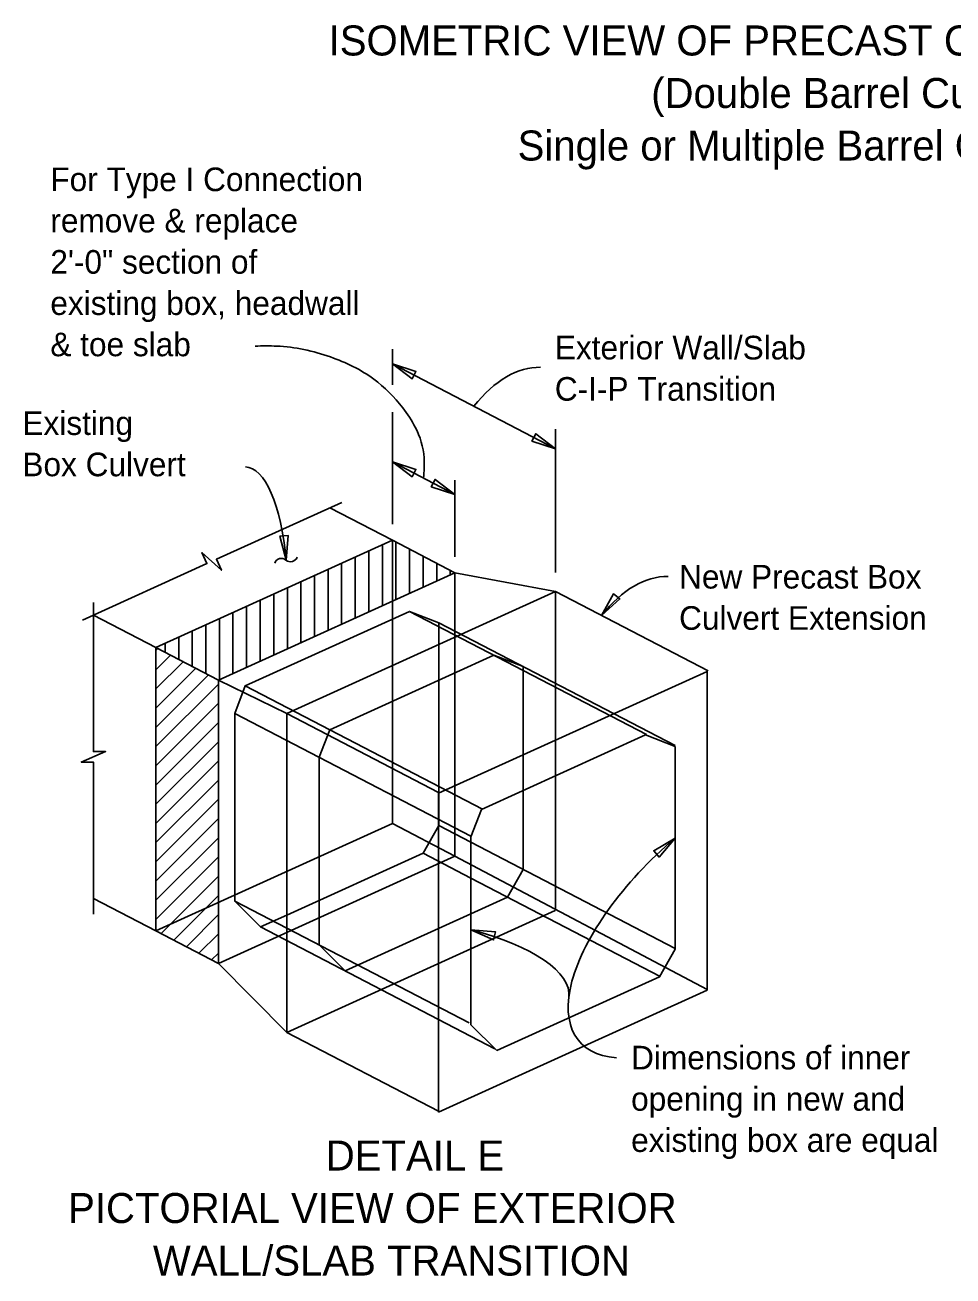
# Model space of a CAD drawing. Extents: x 10050 to 10414, y 76434 to 76519.
# Drawn here: x 10207.9 to 10231.66, y 76436.77 to 76468.78 of the extents above; entities that cross this region are included whole.
import ezdxf

# ---------------------------------------------------------------- set-up
doc = ezdxf.new("R2010")
doc.units = 0
for name, color, linetype in [('AdhocPoint_dp', 7, 'Continuous'), ('Patterning', 7, 'Continuous'), ('PlotBorder_dp', 7, 'Continuous'), ('SubStrConc_h', 7, 'Continuous'), ('Symbols', 7, 'Continuous'), ('TextMisc', 7, 'Continuous')]:
    doc.layers.add(name, color=color, linetype=linetype)

msp = doc.modelspace()

# ---------------------------------------------------------------- linework, layer by layer
at = {"layer": 'AdhocPoint_dp'}
for p, q in [((10217.307, 76455.593), (10215.707, 76456.424)), ((10211.255, 76452.848), (10209.655, 76453.679)), ((10211.255, 76445.597), (10209.655, 76446.428))]:
    msp.add_line(p, q, dxfattribs=at)
at = {"layer": 'Patterning'}
for p, q in [((10217.307, 76460.485), (10217.307, 76459.573)), ((10221.482, 76457.937), (10217.307, 76460.106)), ((10217.307, 76458.875), (10217.307, 76456.008)), ((10221.482, 76458.434), (10221.482, 76454.769)), ((10218.907, 76456.768), (10217.307, 76457.599)), ((10218.907, 76457.129), (10218.907, 76455.171))]:
    msp.add_line(p, q, dxfattribs=at)
for points in [[(10214.584, 76455.086), (10214.638, 76455.717), (10214.427, 76455.7)], [(10222.659, 76453.669), (10223.132, 76454.091), (10222.966, 76454.223)], [(10224.542, 76447.971), (10223.998, 76447.647), (10224.135, 76447.486)], [(10219.317, 76445.623), (10219.897, 76445.368), (10219.949, 76445.573)]]:
    msp.add_lwpolyline(points, close=True, dxfattribs=at)
for centre, major_axis, ratio, start_param, end_param in [((10220.927, 76451.369), (-0.174, -8.651), 0.411326, 3.141808, 3.634993), ((10213.566, 76454.424), (0.022, -3.046), 0.343762, 1.787422, 3.141593), ((10224.192, 76446.016), (-0.174, -8.651), 0.411326, 3.141808, 3.634993), ((10225.886, 76446.109), (3.787, 3.349), 0.45249, 1.52585, 3.559483), ((10217.875, 76444.366), (-3.949, 0.469), 0.376773, 3.141593, 4.383632)]:
    msp.add_ellipse(centre, major_axis=major_axis, ratio=ratio, start_param=start_param, end_param=end_param, dxfattribs=at)
msp.add_spline([(10213.791, 76460.562), (10214.349, 76460.562), (10215.722, 76460.284), (10216.828, 76459.718), (10217.57, 76458.982), (10217.894, 76458.486), (10218.118, 76457.704), (10218.107, 76457.184)], degree=3, dxfattribs=at)
at = {"layer": 'PlotBorder_dp'}
for p, q in [((10211.255, 76452.848), (10217.307, 76455.593)), ((10218.907, 76454.762), (10217.307, 76455.593)), ((10212.855, 76452.017), (10218.907, 76454.762)), ((10218.907, 76454.762), (10221.482, 76454.28)), ((10214.604, 76451.16), (10221.482, 76454.28)), ((10225.391, 76452.25), (10221.482, 76454.28)), ((10211.255, 76452.848), (10211.255, 76445.597)), ((10212.855, 76452.017), (10211.255, 76452.848)), ((10218.489, 76449.119), (10225.367, 76452.239)), ((10225.367, 76452.239), (10225.367, 76444.081)), ((10212.855, 76452.017), (10212.855, 76444.766)), ((10212.855, 76452.017), (10214.604, 76451.16)), ((10214.604, 76451.16), (10214.604, 76443.002)), ((10218.489, 76449.143), (10214.604, 76451.16)), ((10219.589, 76448.706), (10223.789, 76450.611)), ((10224.542, 76450.32), (10223.789, 76450.611)), ((10224.542, 76450.32), (10224.542, 76445.128)), ((10218.489, 76449.119), (10218.489, 76440.961)), ((10220.657, 76449.19), (10220.657, 76447.169)), ((10219.589, 76448.706), (10219.317, 76448.001)), ((10219.317, 76443.196), (10219.317, 76448.001)), ((10219.317, 76447.865), (10224.542, 76445.151)), ((10220.255, 76446.462), (10220.657, 76447.169)), ((10219.317, 76446.949), (10224.164, 76444.432)), ((10219.317, 76446.037), (10220.255, 76446.462)), ((10212.855, 76444.766), (10211.255, 76445.597)), ((10224.14, 76444.421), (10224.542, 76445.128)), ((10212.855, 76444.766), (10214.604, 76443.002)), ((10219.979, 76442.534), (10224.14, 76444.421)), ((10218.489, 76440.961), (10225.367, 76444.081)), ((10218.489, 76440.985), (10214.604, 76443.002)), ((10219.317, 76443.196), (10219.979, 76442.534))]:
    msp.add_line(p, q, dxfattribs=at)
at = {"layer": 'SubStrConc_h'}
for p, q in [((10217.307, 76455.593), (10217.307, 76448.342)), ((10218.907, 76454.762), (10218.907, 76449.947)), ((10221.482, 76454.28), (10221.482, 76446.117)), ((10217.742, 76453.775), (10223.813, 76450.622)), ((10218.495, 76453.484), (10224.542, 76450.344)), ((10215.704, 76450.747), (10219.904, 76452.652)), ((10220.657, 76452.361), (10219.904, 76452.652)), ((10220.657, 76452.361), (10220.657, 76449.19)), ((10213.542, 76451.87), (10219.613, 76448.717)), ((10213.27, 76451.165), (10219.317, 76448.024)), ((10215.704, 76450.747), (10215.432, 76450.042)), ((10215.432, 76445.237), (10215.432, 76450.042)), ((10218.907, 76449.947), (10218.907, 76447.511)), ((10211.255, 76445.597), (10217.307, 76448.342)), ((10217.307, 76448.342), (10218.907, 76447.511)), ((10218.495, 76448.292), (10219.317, 76447.865)), ((10212.855, 76444.766), (10218.907, 76447.511)), ((10218.093, 76447.585), (10219.317, 76446.949)), ((10218.907, 76447.511), (10225.367, 76444.098)), ((10213.27, 76446.36), (10219.269, 76443.244)), ((10214.604, 76443.002), (10221.477, 76446.12)), ((10216.094, 76444.575), (10219.317, 76446.037)), ((10213.932, 76445.698), (10219.931, 76442.582)), ((10215.432, 76445.237), (10216.094, 76444.575))]:
    msp.add_line(p, q, dxfattribs=at)
for points in [[(10218.495, 76452.925), (10218.495, 76453.484), (10217.742, 76453.775), (10213.542, 76451.87), (10213.27, 76451.165), (10213.27, 76446.36), (10213.932, 76445.698), (10214.604, 76446.002)], [(10214.604, 76446.002), (10218.093, 76447.585), (10218.495, 76448.292), (10218.495, 76452.925)]]:
    msp.add_lwpolyline(points, dxfattribs=at)
at = {"layer": 'Symbols'}
for points in [[(10217.307, 76460.106), (10217.812, 76459.724), (10217.91, 76459.912)], [(10221.482, 76457.937), (10220.976, 76458.319), (10220.879, 76458.131)], [(10217.307, 76457.599), (10217.812, 76457.218), (10217.91, 76457.405)], [(10218.907, 76456.768), (10218.401, 76457.15), (10218.303, 76456.963)]]:
    msp.add_lwpolyline(points, close=True, dxfattribs=at)
for points in [[(10209.378, 76453.553), (10212.558, 76454.996), (10212.43, 76455.278), (10212.932, 76454.825), (10212.804, 76455.107), (10216.015, 76456.564)], [(10209.655, 76446.026), (10209.655, 76449.919), (10209.345, 76449.919), (10209.965, 76450.188), (10209.655, 76450.188), (10209.655, 76453.998)]]:
    msp.add_lwpolyline(points, dxfattribs=at)
for centre, start, end in [((10214.466, 76454.951), 48.9165, 160.6437), ((10214.701, 76455.221), 228.9165, 340.6437)]:
    msp.add_arc(centre, 0.179, start, end, dxfattribs=at)
at = {"layer": 'TextMisc'}
for p, q in [((10217.051, 76453.92), (10217.051, 76455.477)), ((10217.398, 76454.078), (10217.398, 76455.545)), ((10216.356, 76453.605), (10216.356, 76455.162)), ((10216.703, 76453.763), (10216.703, 76455.319)), ((10217.746, 76454.236), (10217.746, 76455.365)), ((10218.094, 76454.393), (10218.094, 76455.184)), ((10215.66, 76453.29), (10215.66, 76454.846)), ((10216.008, 76453.447), (10216.008, 76455.004)), ((10218.441, 76454.551), (10218.441, 76455.004)), ((10218.789, 76454.709), (10218.789, 76454.823)), ((10214.965, 76452.974), (10214.965, 76454.531)), ((10215.313, 76453.132), (10215.313, 76454.689)), ((10214.27, 76452.659), (10214.27, 76454.216)), ((10214.618, 76452.816), (10214.618, 76454.373)), ((10213.575, 76452.343), (10213.575, 76453.9)), ((10213.922, 76452.501), (10213.922, 76454.058)), ((10212.88, 76452.028), (10212.88, 76453.585)), ((10213.227, 76452.186), (10213.227, 76453.743)), ((10212.184, 76452.365), (10212.184, 76453.27)), ((10212.532, 76452.185), (10212.532, 76453.427)), ((10211.255, 76452.772), (10211.305, 76452.822)), ((10211.489, 76452.726), (10211.489, 76452.954)), ((10211.837, 76452.546), (10211.837, 76453.112)), ((10211.255, 76452.281), (10211.628, 76452.654)), ((10211.255, 76451.789), (10211.952, 76452.486)), ((10211.255, 76451.297), (10212.275, 76452.318)), ((10211.255, 76450.806), (10212.599, 76452.15)), ((10211.255, 76450.314), (10212.855, 76451.914)), ((10211.255, 76449.823), (10212.855, 76451.423)), ((10211.255, 76449.331), (10212.855, 76450.931)), ((10211.255, 76448.84), (10212.855, 76450.44)), ((10211.255, 76448.348), (10212.855, 76449.948)), ((10211.255, 76447.856), (10212.855, 76449.456)), ((10211.255, 76447.365), (10212.855, 76448.965)), ((10211.255, 76446.873), (10212.855, 76448.473)), ((10211.255, 76446.382), (10212.855, 76447.982)), ((10211.255, 76445.89), (10212.855, 76447.49)), ((10211.386, 76445.529), (10212.855, 76446.998)), ((10211.709, 76445.361), (10212.855, 76446.507)), ((10212.033, 76445.193), (10212.855, 76446.015)), ((10212.356, 76445.025), (10212.855, 76445.524)), ((10212.68, 76444.857), (10212.855, 76445.032))]:
    msp.add_line(p, q, dxfattribs=at)

# ---------------------------------------------------------------- texts
at = {"layer": 'Patterning'}
for s, height, p in [('ISOMETRIC VIEW OF PRECAST CONCRETE BOX CULVERT', 0.768, (10215.674, 76467.999)), ('(Double Barrel Culvert shown,', 0.768, (10223.931, 76466.655)), ('Single or Multiple Barrel Culvert similar)', 0.768, (10220.512, 76465.311)), ('For Type I Connection', 0.6048, (10208.552, 76464.527)), ('remove & replace', 0.6048, (10208.552, 76463.471)), ('2\'-0" section of', 0.6048, (10208.552, 76462.415)), ('existing box, headwall', 0.6048, (10208.552, 76461.359)), ('& toe slab', 0.6048, (10208.552, 76460.303)), ('Exterior Wall/Slab ', 0.6048, (10221.464, 76460.221)), ('C-I-P Transition ', 0.6048, (10221.464, 76459.165)), ('Existing', 0.6048, (10207.837, 76458.288)), ('Box Culvert', 0.6048, (10207.837, 76457.232)), ('New Precast Box', 0.6048, (10224.645, 76454.358)), ('Culvert Extension', 0.6048, (10224.645, 76453.302)), ('Dimensions of inner', 0.6048, (10223.417, 76442.053)), ('opening in new and', 0.6048, (10223.417, 76440.997)), ('existing box are equal', 0.6048, (10223.417, 76439.941)), ('DETAIL E', 0.768, (10215.602, 76439.466)), ('PICTORIAL VIEW OF EXTERIOR', 0.768, (10209.006, 76438.122)), ('WALL/SLAB TRANSITION', 0.768, (10211.177, 76436.778))]:
    msp.add_text(s, height=height, dxfattribs=at).set_placement(p)

doc.saveas('drawing.dxf')
